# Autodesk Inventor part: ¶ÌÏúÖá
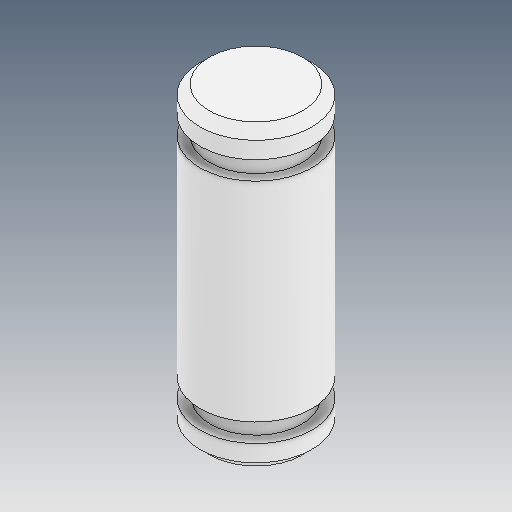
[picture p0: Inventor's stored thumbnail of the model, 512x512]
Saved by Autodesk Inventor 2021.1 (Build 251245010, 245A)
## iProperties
Created: 2021-06
Part Number: ¶ÌÏúÖá
Material: Ogólny
Document SubType Name: Modeling
Designer: user
Density: 1 g/cm^3
Appearance: Domyślna
Author: user
Revision Number: ÈÎºÎ
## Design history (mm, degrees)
feature "ÊäÈë1"
node "Bryła1"
